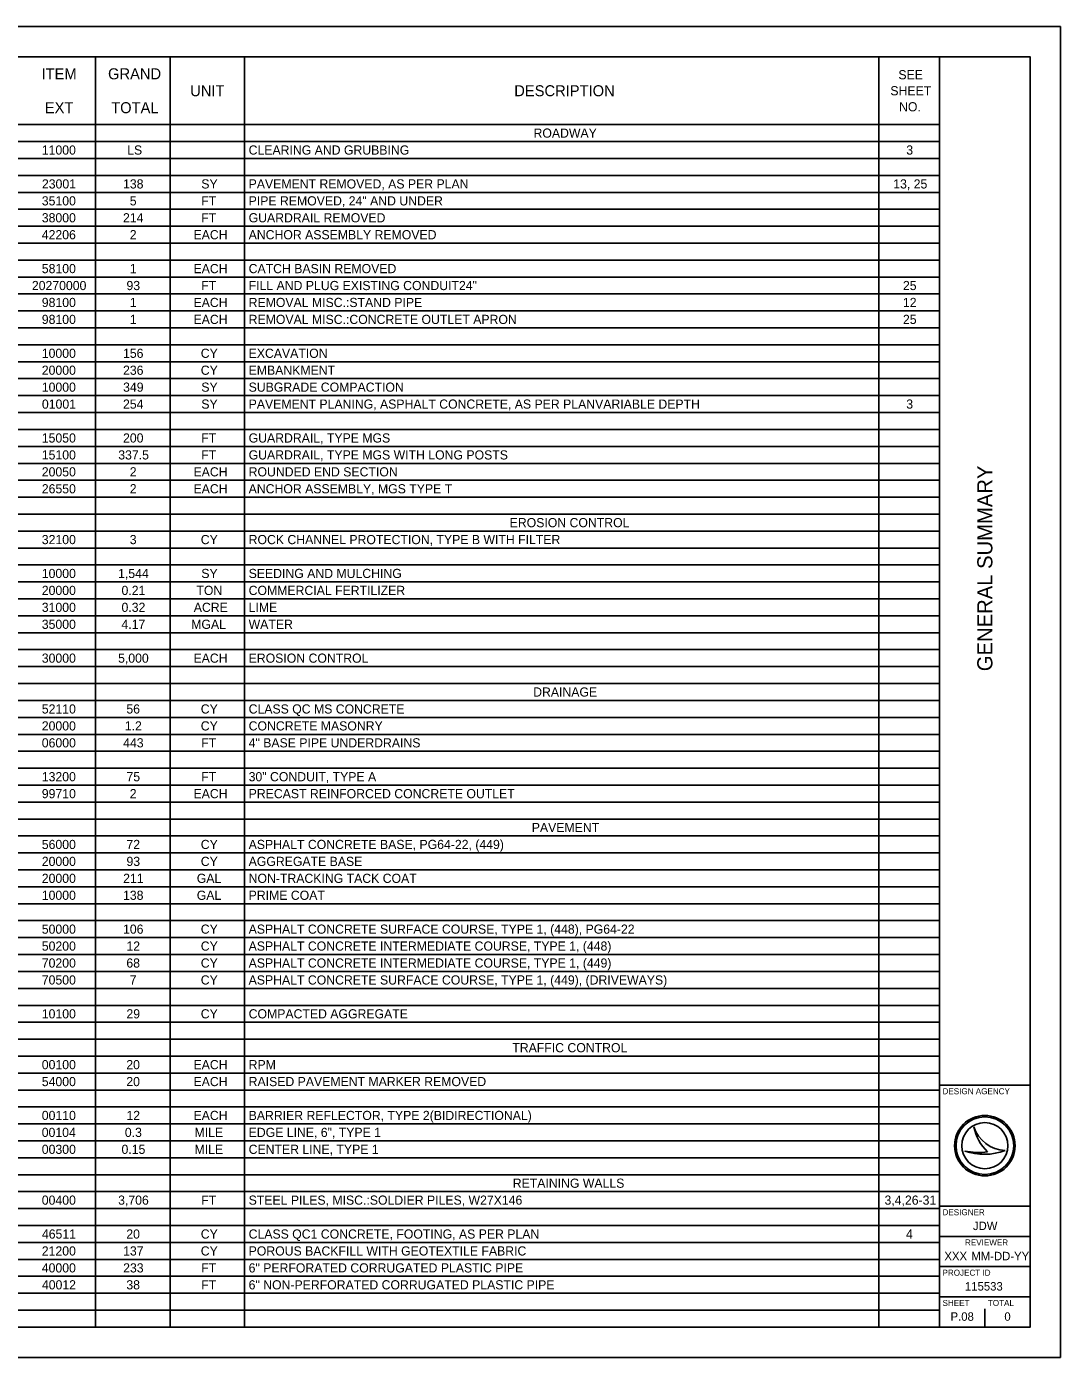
# Model space of a CAD drawing. Extents: x 0 to 34, y 0 to 22.
# Drawn here: x 16.9 to 34, y 0 to 22 of the extents above; entities that cross this region are included whole.
import ezdxf

# ---------------------------------------------------------------- set-up
doc = ezdxf.new("R2010")
doc.units = 0
for name, color, linetype in [('Default', 7, 'Continuous'), ('SH_Border', 7, 'Continuous'), ('SH_Cut_Line', 7, 'Continuous'), ('SH_Data', 7, 'Continuous')]:
    doc.layers.add(name, color=color, linetype=linetype)

msp = doc.modelspace()

# ---------------------------------------------------------------- linework, layer by layer
at = {"layer": 'Default'}
for p, q in [((1.5, 21.5), (32, 21.5)), ((18.035, 21.5), (18.035, 0.5)), ((19.27, 21.5), (19.27, 0.5)), ((20.505, 21.5), (20.505, 0.5)), ((30.995, 21.5), (30.995, 0.5)), ((32, 21.5), (32, 0.5)), ((1.5, 20.38), (32, 20.38)), ((1.5, 20.1), (32, 20.1)), ((1.5, 19.82), (32, 19.82)), ((1.5, 19.54), (32, 19.54)), ((1.5, 19.26), (32, 19.26)), ((1.5, 18.98), (32, 18.98)), ((1.5, 18.7), (32, 18.7)), ((1.5, 18.42), (32, 18.42)), ((1.5, 18.14), (32, 18.14)), ((1.5, 17.86), (32, 17.86)), ((1.5, 17.58), (32, 17.58)), ((1.5, 17.3), (32, 17.3)), ((1.5, 17.02), (32, 17.02)), ((1.5, 16.74), (32, 16.74)), ((1.5, 16.46), (32, 16.46)), ((1.5, 16.18), (32, 16.18)), ((1.5, 15.9), (32, 15.9)), ((1.5, 15.62), (32, 15.62)), ((1.5, 15.34), (32, 15.34)), ((1.5, 15.06), (32, 15.06)), ((1.5, 14.78), (32, 14.78)), ((1.5, 14.5), (32, 14.5)), ((1.5, 14.22), (32, 14.22)), ((1.5, 13.94), (32, 13.94)), ((1.5, 13.66), (32, 13.66)), ((1.5, 13.38), (32, 13.38)), ((1.5, 13.1), (32, 13.1)), ((1.5, 12.82), (32, 12.82)), ((1.5, 12.54), (32, 12.54)), ((1.5, 12.26), (32, 12.26)), ((1.5, 11.98), (32, 11.98)), ((1.5, 11.7), (32, 11.7)), ((1.5, 11.42), (32, 11.42)), ((1.5, 11.14), (32, 11.14)), ((1.5, 10.86), (32, 10.86)), ((1.5, 10.58), (32, 10.58)), ((1.5, 10.3), (32, 10.3)), ((1.5, 10.02), (32, 10.02)), ((1.5, 9.74), (32, 9.74)), ((1.5, 9.46), (32, 9.46)), ((1.5, 9.18), (32, 9.18)), ((1.5, 8.9), (32, 8.9)), ((1.5, 8.62), (32, 8.62)), ((1.5, 8.34), (32, 8.34)), ((1.5, 8.06), (32, 8.06)), ((1.5, 7.78), (32, 7.78)), ((1.5, 7.5), (32, 7.5)), ((1.5, 7.22), (32, 7.22)), ((1.5, 6.94), (32, 6.94)), ((1.5, 6.66), (32, 6.66)), ((1.5, 6.38), (32, 6.38)), ((1.5, 6.1), (32, 6.1)), ((1.5, 5.82), (32, 5.82)), ((1.5, 5.54), (32, 5.54)), ((1.5, 5.26), (32, 5.26)), ((1.5, 4.98), (32, 4.98)), ((1.5, 4.7), (32, 4.7)), ((1.5, 4.42), (32, 4.42)), ((1.5, 4.14), (32, 4.14)), ((1.5, 3.86), (32, 3.86)), ((1.5, 3.58), (32, 3.58)), ((1.5, 3.3), (32, 3.3)), ((1.5, 3.02), (32, 3.02)), ((1.5, 2.74), (32, 2.74)), ((1.5, 2.46), (32, 2.46)), ((1.5, 2.18), (32, 2.18)), ((1.5, 1.9), (32, 1.9)), ((1.5, 1.62), (32, 1.62)), ((1.5, 1.34), (32, 1.34)), ((1.5, 1.06), (32, 1.06)), ((1.5, 0.78), (32, 0.78)), ((1.5, 0.5), (32, 0.5))]:
    msp.add_line(p, q, dxfattribs=at)
at = {"layer": 'SH_Border'}
for p, q in [((32, 0.5), (32, 21.5)), ((32, 4.5), (33.5, 4.5)), ((32, 2.5), (33.5, 2.5)), ((32, 2), (33.5, 2)), ((32, 1.5), (33.5, 1.5)), ((32, 1), (33.5, 1))]:
    msp.add_line(p, q, dxfattribs=at)
msp.add_lwpolyline([(1.5, 21.5), (33.5, 21.5), (33.5, 0.5), (1.5, 0.5)], close=True, dxfattribs=at)
at = {"layer": 'SH_Cut_Line'}
msp.add_lwpolyline([(0, 0), (34, 0), (34, 22), (0, 22)], close=True, dxfattribs=at)
at = {"layer": 'SH_Data'}
for p, q in [((32.567, 3.81), (32.567, 3.81)), ((32.417, 3.41), (32.417, 3.41)), ((32.75, 3.5), (32.75, 3.5)), ((33.087, 3.419), (33.087, 3.419)), ((32.375, 0.675), (32.375, 0.675)), ((32.75, 0.5), (32.75, 0.8))]:
    msp.add_line(p, q, dxfattribs=at)
for radius in [0.5, 0.477, 0.477, 0.382]:
    msp.add_circle((32.75, 3.5), radius, dxfattribs=at)
for centre, radius, start, end in [((33.116, 3.998), 0.58, 198.9257, 198.9319), ((33.347, 3.97), 0.796, 191.6379, 191.6421), ((33.116, 3.998), 0.58, 198.9319, 267.1657), ((33.347, 3.97), 0.796, 191.6421, 226.0947), ((32.739, 4.37), 1.013, 251.4576, 290.0832), ((32.648, 4.654), 1.266, 259.4964, 259.4995), ((32.739, 4.37), 1.013, 251.4527, 251.4576), ((32.648, 4.654), 1.266, 259.4995, 276.6672)]:
    msp.add_arc(centre, radius, start, end, dxfattribs=at)

# ---------------------------------------------------------------- texts
at = {"layer": 'Default'}
for s, height, p in [('ITEM', 0.1818, (17.145, 21.129)), ('GRAND', 0.1818, (18.245, 21.129)), ('SEE ', 0.1515, (31.32, 21.129)), ('UNIT', 0.1818, (19.604, 20.849)), ('DESCRIPTION', 0.18184, (24.965, 20.849)), ('SHEET ', 0.1515, (31.187, 20.864)), ('EXT', 0.1818, (17.199, 20.569)), ('TOTAL', 0.1818, (18.297, 20.569)), ('NO.', 0.1515, (31.331, 20.599)), ('ROADWAY', 0.1515, (25.284, 20.164)), ('11000', 0.1515, (17.149, 19.884)), ('LS', 0.1515, (18.562, 19.884)), ('CLEARING AND GRUBBING', 0.15153, (20.571, 19.884)), ('3', 0.152, (31.45, 19.884)), ('23001', 0.1515, (17.151, 19.324)), ('138', 0.1515, (18.493, 19.324)), ('SY', 0.1515, (19.788, 19.324)), ('PAVEMENT REMOVED, AS PER PLAN', 0.15153, (20.571, 19.324)), ('13, 25', 0.1515, (31.235, 19.324)), ('35100', 0.1515, (17.149, 19.044)), ('5', 0.152, (18.604, 19.044)), ('FT', 0.1515, (19.786, 19.044)), ('PIPE REMOVED, 24" AND UNDER', 0.15153, (20.571, 19.044)), ('38000', 0.1515, (17.149, 18.764)), ('214', 0.1515, (18.492, 18.764)), ('FT', 0.1515, (19.786, 18.764)), ('GUARDRAIL REMOVED', 0.15153, (20.571, 18.764)), ('42206', 0.1515, (17.149, 18.484)), ('2', 0.152, (18.604, 18.484)), ('EACH', 0.1515, (19.659, 18.484)), ('ANCHOR ASSEMBLY REMOVED', 0.15153, (20.571, 18.484)), ('58100', 0.1515, (17.149, 17.924)), ('1', 0.152, (18.604, 17.924)), ('EACH', 0.1515, (19.659, 17.924)), ('CATCH BASIN REMOVED', 0.15153, (20.571, 17.924)), ('20270000', 0.1515, (16.985, 17.644)), ('93', 0.1515, (18.55, 17.644)), ('FT', 0.1515, (19.786, 17.644)), ('FILL AND PLUG EXISTING CONDUIT24"', 0.15153, (20.571, 17.644)), ('25', 0.1515, (31.395, 17.644)), ('98100', 0.1515, (17.149, 17.364)), ('1', 0.152, (18.604, 17.364)), ('EACH', 0.1515, (19.659, 17.364)), ('REMOVAL MISC.:STAND PIPE', 0.15153, (20.571, 17.364)), ('12', 0.1515, (31.395, 17.364)), ('98100', 0.1515, (17.149, 17.084)), ('1', 0.152, (18.604, 17.084)), ('EACH', 0.1515, (19.659, 17.084)), ('REMOVAL MISC.:CONCRETE OUTLET APRON', 0.15153, (20.571, 17.084)), ('25', 0.1515, (31.395, 17.084)), ('10000', 0.1515, (17.149, 16.524)), ('156', 0.1515, (18.493, 16.524)), ('CY', 0.1515, (19.779, 16.524)), ('EXCAVATION', 0.1515, (20.571, 16.524)), ('20000', 0.1515, (17.149, 16.244)), ('236', 0.1515, (18.493, 16.244)), ('CY', 0.1515, (19.779, 16.244)), ('EMBANKMENT', 0.1515, (20.571, 16.244)), ('10000', 0.1515, (17.149, 15.964)), ('349', 0.1515, (18.494, 15.964)), ('SY', 0.1515, (19.788, 15.964)), ('SUBGRADE COMPACTION', 0.15153, (20.571, 15.964)), ('01001', 0.1515, (17.151, 15.684)), ('254', 0.1515, (18.492, 15.684)), ('SY', 0.1515, (19.788, 15.684)), ('PAVEMENT PLANING, ASPHALT CONCRETE, AS PER PLANVARIABLE DEPTH', 0.15153, (20.571, 15.684)), ('3', 0.152, (31.45, 15.684)), ('15050', 0.1515, (17.149, 15.124)), ('200', 0.1515, (18.493, 15.124)), ('FT', 0.1515, (19.786, 15.124)), ('GUARDRAIL, TYPE MGS', 0.15153, (20.571, 15.124)), ('15100', 0.1515, (17.149, 14.844)), ('337.5', 0.1515, (18.414, 14.844)), ('FT', 0.1515, (19.786, 14.844)), ('GUARDRAIL, TYPE MGS WITH LONG POSTS', 0.15153, (20.571, 14.844)), ('20050', 0.1515, (17.149, 14.564)), ('2', 0.152, (18.604, 14.564)), ('EACH', 0.1515, (19.659, 14.564)), ('ROUNDED END SECTION', 0.15153, (20.571, 14.564)), ('26550', 0.1515, (17.149, 14.284)), ('2', 0.152, (18.604, 14.284)), ('EACH', 0.1515, (19.659, 14.284)), ('ANCHOR ASSEMBLY, MGS TYPE T', 0.15153, (20.571, 14.284)), ('EROSION CONTROL', 0.15153, (24.889, 13.724)), ('32100', 0.1515, (17.149, 13.444)), ('3', 0.152, (18.604, 13.444)), ('CY', 0.1515, (19.779, 13.444)), ('ROCK CHANNEL PROTECTION, TYPE B WITH FILTER', 0.15153, (20.571, 13.444)), ('10000', 0.1515, (17.149, 12.884)), ('1,544', 0.1515, (18.411, 12.884)), ('SY', 0.1515, (19.788, 12.884)), ('SEEDING AND MULCHING', 0.15153, (20.571, 12.884)), ('20000', 0.1515, (17.149, 12.604)), ('0.21', 0.1515, (18.468, 12.604)), ('TON', 0.1515, (19.707, 12.604)), ('COMMERCIAL FERTILIZER', 0.15153, (20.571, 12.604)), ('31000', 0.1515, (17.149, 12.324)), ('0.32', 0.1515, (18.468, 12.324)), ('ACRE', 0.1515, (19.663, 12.324)), ('LIME', 0.1515, (20.571, 12.324)), ('35000', 0.1515, (17.149, 12.044)), ('4.17', 0.1515, (18.467, 12.044)), ('MGAL', 0.1515, (19.621, 12.044)), ('WATER', 0.1515, (20.571, 12.044)), ('30000', 0.1515, (17.149, 11.484)), ('5,000', 0.1515, (18.411, 11.484)), ('EACH', 0.1515, (19.659, 11.484)), ('EROSION CONTROL', 0.15153, (20.571, 11.484)), ('DRAINAGE', 0.1515, (25.278, 10.924)), ('52110', 0.1515, (17.149, 10.644)), ('56', 0.1515, (18.548, 10.644)), ('CY', 0.1515, (19.779, 10.644)), ('CLASS QC MS CONCRETE', 0.15153, (20.571, 10.644)), ('20000', 0.1515, (17.149, 10.364)), ('1.2', 0.1515, (18.522, 10.364)), ('CY', 0.1515, (19.779, 10.364)), ('CONCRETE MASONRY', 0.15153, (20.571, 10.364)), ('06000', 0.1515, (17.149, 10.084)), ('443', 0.1515, (18.495, 10.084)), ('FT', 0.1515, (19.786, 10.084)), ('4" BASE PIPE UNDERDRAINS', 0.15153, (20.571, 10.084)), ('13200', 0.1515, (17.149, 9.524)), ('75', 0.1515, (18.55, 9.524)), ('FT', 0.1515, (19.786, 9.524)), ('30" CONDUIT, TYPE A', 0.15153, (20.571, 9.524)), ('99710', 0.1515, (17.149, 9.244)), ('2', 0.152, (18.604, 9.244)), ('EACH', 0.1515, (19.659, 9.244)), ('PRECAST REINFORCED CONCRETE OUTLET', 0.15153, (20.571, 9.244)), ('PAVEMENT', 0.1515, (25.255, 8.684)), ('56000', 0.1515, (17.149, 8.404)), ('72', 0.1515, (18.549, 8.404)), ('CY', 0.1515, (19.779, 8.404)), ('ASPHALT CONCRETE BASE, PG64-22, (449)', 0.15153, (20.571, 8.404)), ('20000', 0.1515, (17.149, 8.124)), ('93', 0.1515, (18.55, 8.124)), ('CY', 0.1515, (19.779, 8.124)), ('AGGREGATE BASE', 0.15153, (20.571, 8.124)), ('20000', 0.1515, (17.149, 7.844)), ('211', 0.1515, (18.495, 7.844)), ('GAL', 0.1515, (19.713, 7.844)), ('NON-TRACKING TACK COAT', 0.15153, (20.571, 7.844)), ('10000', 0.1515, (17.149, 7.564)), ('138', 0.1515, (18.493, 7.564)), ('GAL', 0.1515, (19.713, 7.564)), ('PRIME COAT', 0.1515, (20.571, 7.564)), ('50000', 0.1515, (17.149, 7.004)), ('106', 0.1515, (18.493, 7.004)), ('CY', 0.1515, (19.779, 7.004)), ('ASPHALT CONCRETE SURFACE COURSE, TYPE 1, (448), PG64-22', 0.15153, (20.571, 7.004)), ('50200', 0.1515, (17.149, 6.724)), ('12', 0.1515, (18.549, 6.724)), ('CY', 0.1515, (19.779, 6.724)), ('ASPHALT CONCRETE INTERMEDIATE COURSE, TYPE 1, (448)', 0.15153, (20.571, 6.724)), ('ASPHALT CONCRETE INTERMEDIATE COURSE, TYPE 1, (449)', 0.15153, (20.571, 6.444)), ('70200', 0.1515, (17.149, 6.444)), ('68', 0.1515, (18.548, 6.444)), ('CY', 0.1515, (19.779, 6.444)), ('70500', 0.1515, (17.149, 6.164)), ('7', 0.152, (18.603, 6.164)), ('CY', 0.1515, (19.779, 6.164)), ('ASPHALT CONCRETE SURFACE COURSE, TYPE 1, (449), (DRIVEWAYS)', 0.15153, (20.571, 6.164)), ('10100', 0.1515, (17.149, 5.604)), ('29', 0.1515, (18.549, 5.604)), ('CY', 0.1515, (19.779, 5.604)), ('COMPACTED AGGREGATE', 0.15153, (20.571, 5.604)), ('TRAFFIC CONTROL', 0.15153, (24.933, 5.044)), ('00100', 0.1515, (17.149, 4.764)), ('20', 0.1515, (18.547, 4.764)), ('EACH', 0.1515, (19.659, 4.764)), ('RPM', 0.1515, (20.571, 4.764)), ('54000', 0.1515, (17.149, 4.484)), ('20', 0.1515, (18.547, 4.484)), ('EACH', 0.1515, (19.659, 4.484)), ('RAISED PAVEMENT MARKER REMOVED', 0.15153, (20.571, 4.484)), ('00110', 0.1515, (17.149, 3.924)), ('12', 0.1515, (18.549, 3.924)), ('EACH', 0.1515, (19.659, 3.924)), ('BARRIER REFLECTOR, TYPE 2(BIDIRECTIONAL)', 0.15153, (20.571, 3.924)), ('00104', 0.1515, (17.148, 3.644)), ('0.3', 0.1515, (18.523, 3.644)), ('MILE', 0.1515, (19.676, 3.644)), ('EDGE LINE, 6", TYPE 1', 0.15153, (20.571, 3.644)), ('00300', 0.1515, (17.149, 3.364)), ('0.15', 0.1515, (18.468, 3.364)), ('MILE', 0.1515, (19.676, 3.364)), ('CENTER LINE, TYPE 1', 0.15153, (20.571, 3.364)), ('RETAINING WALLS', 0.15153, (24.94, 2.804)), ('00400', 0.1515, (17.149, 2.524)), ('3,706', 0.1515, (18.412, 2.524)), ('FT', 0.1515, (19.786, 2.524)), ('STEEL PILES, MISC.:SOLDIER PILES, W27X146', 0.15153, (20.571, 2.524)), ('3,4,26-31', 0.1515, (31.09, 2.524)), ('46511', 0.1515, (17.151, 1.964)), ('20', 0.1515, (18.547, 1.964)), ('CY', 0.1515, (19.779, 1.964)), ('CLASS QC1 CONCRETE, FOOTING, AS PER PLAN', 0.15153, (20.571, 1.964)), ('4', 0.152, (31.446, 1.964)), ('21200', 0.1515, (17.149, 1.684)), ('137', 0.1515, (18.494, 1.684)), ('CY', 0.1515, (19.779, 1.684)), ('POROUS BACKFILL WITH GEOTEXTILE FABRIC', 0.15153, (20.571, 1.684)), ('40000', 0.1515, (17.149, 1.404)), ('233', 0.1515, (18.495, 1.404)), ('FT', 0.1515, (19.786, 1.404)), ('6" PERFORATED CORRUGATED PLASTIC PIPE', 0.15153, (20.571, 1.404)), ('40012', 0.1515, (17.151, 1.124)), ('38', 0.1515, (18.548, 1.124)), ('FT', 0.1515, (19.786, 1.124)), ('6" NON-PERFORATED CORRUGATED PLASTIC PIPE', 0.15153, (20.571, 1.124))]:
    msp.add_text(s, height=height, dxfattribs=at).set_placement(p)
at = {"layer": 'SH_Data'}
msp.add_text('GENERAL SUMMARY', height=0.25, rotation=90, dxfattribs=at).set_placement((32.875, 11.344))
for s, height, p in [('DESIGN AGENCY', 0.1, (32.05, 4.35)), ('DESIGNER', 0.1, (32.05, 2.35)), ('JDW', 0.14, (32.553, 2.105)), ('REVIEWER', 0.1, (32.422, 1.85)), ('XXX', 0.14, (32.081, 1.605)), ('MM-DD-YY', 0.14, (32.527, 1.605)), ('PROJECT ID', 0.1, (32.05, 1.35)), ('115533', 0.14, (32.421, 1.105)), ('SHEET', 0.1, (32.05, 0.85)), ('TOTAL', 0.1, (32.8, 0.85)), ('P.08', 0.14, (32.183, 0.605)), ('0', 0.14, (33.073, 0.605))]:
    msp.add_text(s, height=height, dxfattribs=at).set_placement(p)

doc.saveas('drawing.dxf')
